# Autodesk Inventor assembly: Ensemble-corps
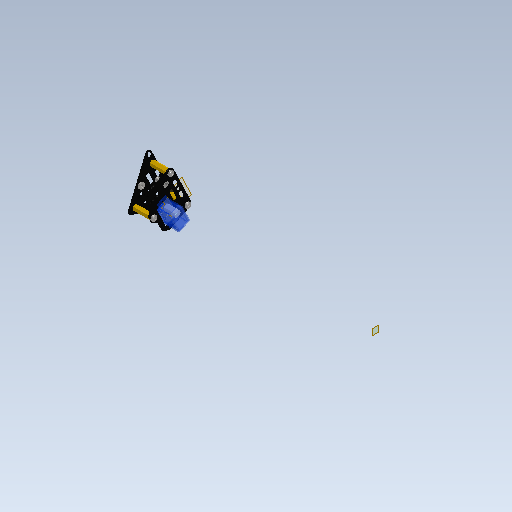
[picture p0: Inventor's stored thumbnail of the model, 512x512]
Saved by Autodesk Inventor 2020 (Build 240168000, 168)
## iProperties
Created: 2021-10
Part Number: Ensemble-corps
Document SubType Name: Assembly
Designer: bruno
Mass: 9.22633 g
Surface Area: 139.573 cm^2
Volume: 5.93462 cm^3
Density: 1.55466 g/cm^3
Author: bruno
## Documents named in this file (6)
- C:\Users\bruno\OneDrive\Bureau\Robot-Inventor\Robot-equillibrage\Ensemble-corps.iam
- C:\Users\bruno\OneDrive\Bureau\Robot-Inventor\Robot-equillibrage\Ensemble-support-servo.iam
- C:\Users\bruno\OneDrive\Bureau\Robot-Inventor\Robot-equillibrage\Servo\Servo.iam
- C:\Users\bruno\OneDrive\Bureau\Robot-Inventor\Robot-equillibrage\ecrou-hexa.ipt
- C:\Users\bruno\OneDrive\Bureau\Robot-Inventor\Robot-equillibrage\plaque-triangle.ipt
- C:\Users\bruno\Documents\Inventor\Content Center Files\R2020\fr-FR\ANSI B18.6.7M(01)\ANSI B18.6.7M - M3x0,5 x 5(5).ipt
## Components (12 placed, 5 different names)
1. Ensemble-support-servo:1 [sub-assembly] — Placage:1, Logement:1, Logement:2, Logement:3, Placage:5, Placage:6, Placage:7, Angle:1, Placage:10, Placage:13
2. Servo:1 [sub-assembly] — Placage:1, Placage:5
3. ecrou-hexa:1 — Logement:3, Placage:12, Placage:16
4. ecrou-hexa:2 — Logement:1, Placage:8, Placage:9, Placage:15
5. ecrou-hexa:3 — Logement:2, Placage:11, Placage:14
6. plaque-triangle:1 — Placage:8, Placage:9, Angle:1, Placage:17, Placage:18, Placage:19
7. Vis à tête tronconique à empreinte cruciforme - Type IA - Métrique M3x0,5 x 5:1 — Placage:6, Placage:7
8. Vis à tête tronconique à empreinte cruciforme - Type IA - Métrique M3x0,5 x 5:2 — Placage:10, Placage:11
9. Vis à tête tronconique à empreinte cruciforme - Type IA - Métrique M3x0,5 x 5:3 — Placage:12, Placage:13
10. Vis à tête tronconique à empreinte cruciforme - Type IA - Métrique M3x0,5 x 5:4 — Placage:14, Placage:19
11. Vis à tête tronconique à empreinte cruciforme - Type IA - Métrique M3x0,5 x 5:5 — Placage:15, Placage:18
12. Vis à tête tronconique à empreinte cruciforme - Type IA - Métrique M3x0,5 x 5:6 — Placage:16, Placage:17
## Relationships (20: Mate 16, Insert 3, Angle 1)
- Placage:1 [Mate]: Ensemble-support-servo:1 ↔ Servo:1
- Logement:1 [Insert]: Ensemble-support-servo:1 ↔ ecrou-hexa:2
- Logement:2 [Insert]: Ensemble-support-servo:1 ↔ ecrou-hexa:3
- Logement:3 [Insert]: Ensemble-support-servo:1 ↔ ecrou-hexa:1
- Placage:5 [Mate]: Ensemble-support-servo:1 ↔ Servo:1
- Placage:6 [Mate]: Ensemble-support-servo:1 ↔ Vis à tête tronconique à empreinte cruciforme - Type IA - Métrique M3x0,5 x 5:1
- Placage:7 [Mate]: Ensemble-support-servo:1 ↔ Vis à tête tronconique à empreinte cruciforme - Type IA - Métrique M3x0,5 x 5:1
- Placage:8 [Mate]: ecrou-hexa:2 ↔ plaque-triangle:1
- Placage:9 [Mate]: ecrou-hexa:2 ↔ plaque-triangle:1
- Angle:1: Ensemble-support-servo:1 ↔ plaque-triangle:1
- Placage:10 [Mate]: Ensemble-support-servo:1 ↔ Vis à tête tronconique à empreinte cruciforme - Type IA - Métrique M3x0,5 x 5:2
- Placage:11 [Mate]: ecrou-hexa:3 ↔ Vis à tête tronconique à empreinte cruciforme - Type IA - Métrique M3x0,5 x 5:2
- Placage:12 [Mate]: ecrou-hexa:1 ↔ Vis à tête tronconique à empreinte cruciforme - Type IA - Métrique M3x0,5 x 5:3
- Placage:13 [Mate]: Ensemble-support-servo:1 ↔ Vis à tête tronconique à empreinte cruciforme - Type IA - Métrique M3x0,5 x 5:3
- Placage:14 [Mate]: ecrou-hexa:3 ↔ Vis à tête tronconique à empreinte cruciforme - Type IA - Métrique M3x0,5 x 5:4
- Placage:15 [Mate]: ecrou-hexa:2 ↔ Vis à tête tronconique à empreinte cruciforme - Type IA - Métrique M3x0,5 x 5:5
- Placage:16 [Mate]: ecrou-hexa:1 ↔ Vis à tête tronconique à empreinte cruciforme - Type IA - Métrique M3x0,5 x 5:6
- Placage:17 [Mate]: plaque-triangle:1 ↔ Vis à tête tronconique à empreinte cruciforme - Type IA - Métrique M3x0,5 x 5:6
- Placage:18 [Mate]: plaque-triangle:1 ↔ Vis à tête tronconique à empreinte cruciforme - Type IA - Métrique M3x0,5 x 5:5
- Placage:19 [Mate]: plaque-triangle:1 ↔ Vis à tête tronconique à empreinte cruciforme - Type IA - Métrique M3x0,5 x 5:4
